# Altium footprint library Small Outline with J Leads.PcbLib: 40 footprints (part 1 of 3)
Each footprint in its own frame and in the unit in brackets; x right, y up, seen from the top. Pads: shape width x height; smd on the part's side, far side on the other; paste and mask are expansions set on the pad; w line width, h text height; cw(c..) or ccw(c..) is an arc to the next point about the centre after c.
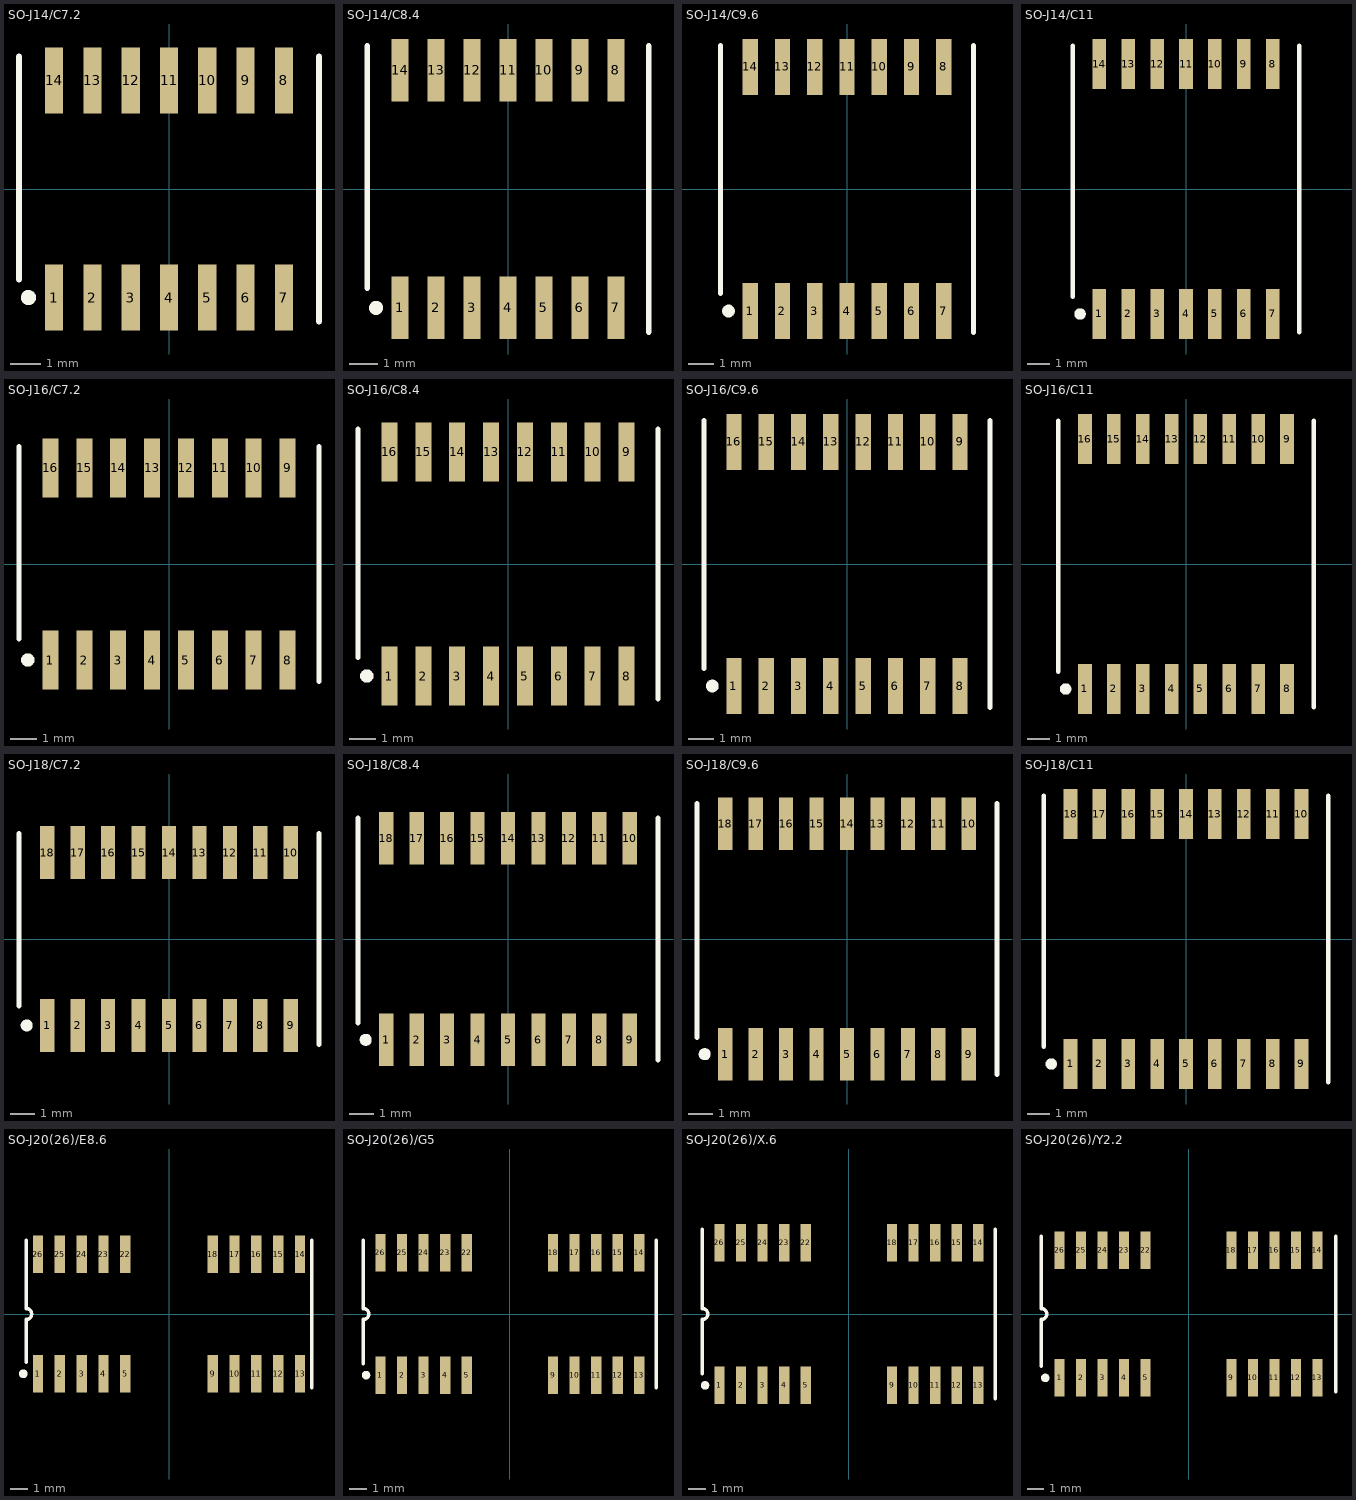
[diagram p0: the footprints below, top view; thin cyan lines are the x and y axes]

## SO-J14/C7.2 [mm]
pads (14):
  rect 0.6x2.2 smd: 1(-3.81,-3.6) 2(-2.54,-3.6) 3(-1.27,-3.6) 4(0,-3.6) 5(1.27,-3.6) 6(2.54,-3.6) 7(3.81,-3.6) 8(3.81,3.6) 9(2.54,3.6) 10(1.27,3.6) 11(0,3.6) 12(-1.27,3.6) 13(-2.54,3.6) 14(-3.81,3.6)
Top Overlay:
  circle w0.25: c-4.66,-3.6 r0.125
  lines w0.2: -4.975,-3 -4.975,4.4 ; 4.975,-4.4 4.975,4.4

## SO-J14/C8.4 [mm]
pads (14):
  rect 0.6x2.2 smd: 1(-3.81,-4.2) 2(-2.54,-4.2) 3(-1.27,-4.2) 4(0,-4.2) 5(1.27,-4.2) 6(2.54,-4.2) 7(3.81,-4.2) 8(3.81,4.2) 9(2.54,4.2) 10(1.27,4.2) 11(0,4.2) 12(-1.27,4.2) 13(-2.54,4.2) 14(-3.81,4.2)
Top Overlay:
  circle w0.25: c-4.66,-4.2 r0.125
  lines w0.2: -4.975,-3.5 -4.975,5.05 ; 4.975,-5.05 4.975,5.05

## SO-J14/C9.6 [mm]
pads (14):
  rect 0.6x2.2 smd: 1(-3.81,-4.8) 2(-2.54,-4.8) 3(-1.27,-4.8) 4(0,-4.8) 5(1.27,-4.8) 6(2.54,-4.8) 7(3.81,-4.8) 8(3.81,4.8) 9(2.54,4.8) 10(1.27,4.8) 11(0,4.8) 12(-1.27,4.8) 13(-2.54,4.8) 14(-3.81,4.8)
Top Overlay:
  circle w0.25: c-4.66,-4.8 r0.125
  lines w0.2: -4.975,-4.1 -4.975,5.65 ; 4.975,-5.65 4.975,5.65

## SO-J14/C11 [mm]
pads (14):
  rect 0.6x2.2 smd: 1(-3.81,-5.5) 2(-2.54,-5.5) 3(-1.27,-5.5) 4(0,-5.5) 5(1.27,-5.5) 6(2.54,-5.5) 7(3.81,-5.5) 8(3.81,5.5) 9(2.54,5.5) 10(1.27,5.5) 11(0,5.5) 12(-1.27,5.5) 13(-2.54,5.5) 14(-3.81,5.5)
Top Overlay:
  circle w0.25: c-4.66,-5.5 r0.125
  lines w0.2: -4.975,-4.75 -4.975,6.3 ; 4.975,-6.3 4.975,6.3

## SO-J16/C7.2 [mm]
pads (16):
  rect 0.6x2.2 smd: 1(-4.445,-3.6) 2(-3.175,-3.6) 3(-1.905,-3.6) 4(-0.635,-3.6) 5(0.635,-3.6) 6(1.905,-3.6) 7(3.175,-3.6) 8(4.445,-3.6) 9(4.445,3.6) 10(3.175,3.6) 11(1.905,3.6) 12(0.635,3.6) 13(-0.635,3.6) 14(-1.905,3.6) 15(-3.175,3.6) 16(-4.445,3.6)
Top Overlay:
  circle w0.25: c-5.295,-3.6 r0.125
  lines w0.2: -5.625,-2.8 -5.625,4.4 ; 5.625,-4.4 5.625,4.4

## SO-J16/C8.4 [mm]
pads (16):
  rect 0.6x2.2 smd: 1(-4.445,-4.2) 2(-3.175,-4.2) 3(-1.905,-4.2) 4(-0.635,-4.2) 5(0.635,-4.2) 6(1.905,-4.2) 7(3.175,-4.2) 8(4.445,-4.2) 9(4.445,4.2) 10(3.175,4.2) 11(1.905,4.2) 12(0.635,4.2) 13(-0.635,4.2) 14(-1.905,4.2) 15(-3.175,4.2) 16(-4.445,4.2)
Top Overlay:
  circle w0.25: c-5.295,-4.2 r0.125
  lines w0.2: -5.625,-3.5 -5.625,5.05 ; 5.625,-5.05 5.625,5.05

## SO-J16/C9.6 [mm]
pads (16):
  rect 0.6x2.2 smd: 1(-4.445,-4.8) 2(-3.175,-4.8) 3(-1.905,-4.8) 4(-0.635,-4.8) 5(0.635,-4.8) 6(1.905,-4.8) 7(3.175,-4.8) 8(4.445,-4.8) 9(4.445,4.8) 10(3.175,4.8) 11(1.905,4.8) 12(0.635,4.8) 13(-0.635,4.8) 14(-1.905,4.8) 15(-3.175,4.8) 16(-4.445,4.8)
Top Overlay:
  circle w0.25: c-5.295,-4.8 r0.125
  lines w0.2: -5.625,-4.1 -5.625,5.65 ; 5.625,-5.65 5.625,5.65

## SO-J16/C11 [mm]
pads (16):
  rect 0.6x2.2 smd: 1(-4.445,-5.5) 2(-3.175,-5.5) 3(-1.905,-5.5) 4(-0.635,-5.5) 5(0.635,-5.5) 6(1.905,-5.5) 7(3.175,-5.5) 8(4.445,-5.5) 9(4.445,5.5) 10(3.175,5.5) 11(1.905,5.5) 12(0.635,5.5) 13(-0.635,5.5) 14(-1.905,5.5) 15(-3.175,5.5) 16(-4.445,5.5)
Top Overlay:
  circle w0.25: c-5.295,-5.5 r0.125
  lines w0.2: -5.625,-4.75 -5.625,6.3 ; 5.625,-6.3 5.625,6.3

## SO-J18/C7.2 [mm]
pads (18):
  rect 0.6x2.2 smd: 1(-5.08,-3.6) 2(-3.81,-3.6) 3(-2.54,-3.6) 4(-1.27,-3.6) 5(0,-3.6) 6(1.27,-3.6) 7(2.54,-3.6) 8(3.81,-3.6) 9(5.08,-3.6) 10(5.08,3.6) 11(3.81,3.6) 12(2.54,3.6) 13(1.27,3.6) 14(0,3.6) 15(-1.27,3.604) 16(-2.54,3.6) 17(-3.81,3.6) 18(-5.08,3.6)
Top Overlay:
  circle w0.25: c-5.93,-3.6 r0.125
  lines w0.2: -6.25,-2.8 -6.25,4.4 ; 6.25,-4.4 6.25,4.4

## SO-J18/C8.4 [mm]
pads (18):
  rect 0.6x2.2 smd: 1(-5.08,-4.2) 2(-3.81,-4.2) 3(-2.54,-4.2) 4(-1.27,-4.2) 5(0,-4.2) 6(1.27,-4.2) 7(2.54,-4.2) 8(3.81,-4.2) 9(5.08,-4.2) 10(5.08,4.2) 11(3.81,4.2) 12(2.54,4.2) 13(1.27,4.2) 14(0,4.2) 15(-1.27,4.2) 16(-2.54,4.2) 17(-3.81,4.2) 18(-5.08,4.2)
Top Overlay:
  circle w0.25: c-5.93,-4.2 r0.125
  lines w0.2: -6.25,-3.5 -6.25,5.05 ; 6.25,-5.05 6.25,5.05

## SO-J18/C9.6 [mm]
pads (18):
  rect 0.6x2.2 smd: 1(-5.08,-4.8) 2(-3.81,-4.8) 3(-2.54,-4.8) 4(-1.27,-4.8) 5(0,-4.8) 6(1.27,-4.8) 7(2.54,-4.8) 8(3.81,-4.8) 9(5.08,-4.8) 10(5.08,4.8) 11(3.81,4.8) 12(2.54,4.8) 13(1.27,4.8) 14(0,4.8) 15(-1.27,4.8) 16(-2.54,4.8) 17(-3.81,4.8) 18(-5.08,4.8)
Top Overlay:
  circle w0.25: c-5.93,-4.8 r0.125
  lines w0.2: -6.25,-4.1 -6.25,5.65 ; 6.25,-5.65 6.25,5.65

## SO-J18/C11 [mm]
pads (18):
  rect 0.6x2.2 smd: 1(-5.08,-5.5) 2(-3.81,-5.5) 3(-2.54,-5.5) 4(-1.27,-5.5) 5(0,-5.5) 6(1.27,-5.5) 7(2.54,-5.5) 8(3.81,-5.5) 9(5.08,-5.5) 10(5.08,5.5) 11(3.81,5.5) 12(2.54,5.5) 13(1.27,5.5) 14(0,5.5) 15(-1.27,5.5) 16(-2.54,5.5) 17(-3.81,5.5) 18(-5.08,5.5)
Top Overlay:
  circle w0.25: c-5.93,-5.5 r0.125
  lines w0.2: -6.25,-4.75 -6.25,6.3 ; 6.25,-6.3 6.25,6.3

## SO-J20(26)/E8.6 [mm]
pads (20):
  rect 0.6x2.2 smd: 1(-7.62,-3.475) 2(-6.35,-3.475) 3(-5.08,-3.475) 4(-3.81,-3.475) 5(-2.54,-3.475) 9(2.54,-3.475) 10(3.81,-3.475) 11(5.08,-3.475) 12(6.35,-3.475) 13(7.62,-3.475) 14(7.62,3.475) 15(6.35,3.475) 16(5.08,3.475) 17(3.81,3.475) 18(2.54,3.475) 22(-2.54,3.475) 23(-3.81,3.475) 24(-5.08,3.475) 25(-6.35,3.475) 26(-7.62,3.475)
Top Overlay:
  circle w0.25: c-8.47,-3.475 r0.125
  lines w0.2: -8.3,-2.8 -8.3,-0.318 ccw(c-8.3,0) -8.3,0.318 -8.3,4.3 ; 8.3,-4.3 8.3,4.3

## SO-J20(26)/G5 [mm]
pads (20):
  rect 0.6x2.2 smd: 1(-7.62,-3.6) 2(-6.35,-3.6) 3(-5.08,-3.6) 4(-3.81,-3.6) 5(-2.54,-3.6) 9(2.54,-3.6) 10(3.81,-3.6) 11(5.08,-3.6) 12(6.35,-3.6) 13(7.62,-3.6) 14(7.62,3.6) 15(6.35,3.6) 16(5.08,3.6) 17(3.81,3.6) 18(2.54,3.6) 22(-2.54,3.6) 23(-3.81,3.6) 24(-5.08,3.6) 25(-6.35,3.6) 26(-7.62,3.6)
Top Overlay:
  circle w0.25: c-8.47,-3.6 r0.125
  lines w0.2: -8.625,-2.925 -8.625,-0.317 ccw(c-8.625,0) -8.625,0.318 -8.625,4.35 ; 8.625,-4.35 8.625,4.35

## SO-J20(26)/X.6 [mm]
pads (20):
  rect 0.6x2.2 smd: 1(-7.62,-4.2) 2(-6.35,-4.2) 3(-5.08,-4.2) 4(-3.81,-4.2) 5(-2.54,-4.2) 9(2.54,-4.2) 10(3.81,-4.2) 11(5.08,-4.2) 12(6.35,-4.2) 13(7.62,-4.2) 14(7.62,4.2) 15(6.35,4.2) 16(5.08,4.2) 17(3.81,4.2) 18(2.54,4.2) 22(-2.54,4.2) 23(-3.81,4.2) 24(-5.08,4.2) 25(-6.35,4.2) 26(-7.62,4.2)
Top Overlay:
  circle w0.25: c-8.47,-4.2 r0.125
  lines w0.2: -8.625,-3.525 -8.625,-0.318 ccw(c-8.625,0) -8.625,0.318 -8.625,5 ; 8.625,-5 8.625,5

## SO-J20(26)/Y2.2 [mm]
pads (20):
  rect 0.6x2.2 smd: 1(-7.62,-3.775) 2(-6.35,-3.775) 3(-5.08,-3.775) 4(-3.81,-3.775) 5(-2.54,-3.775) 9(2.54,-3.775) 10(3.81,-3.775) 11(5.08,-3.775) 12(6.35,-3.775) 13(7.62,-3.775) 14(7.62,3.775) 15(6.35,3.775) 16(5.08,3.775) 17(3.81,3.775) 18(2.54,3.775) 22(-2.54,3.775) 23(-3.81,3.775) 24(-5.08,3.775) 25(-6.35,3.775) 26(-7.62,3.775)
Top Overlay:
  circle w0.25: c-8.47,-3.775 r0.125
  lines w0.2: -8.7,-3.1 -8.7,-0.318 ccw(c-8.7,0) -8.7,0.318 -8.7,4.6 ; 8.7,-4.6 8.7,4.6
